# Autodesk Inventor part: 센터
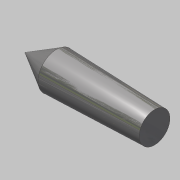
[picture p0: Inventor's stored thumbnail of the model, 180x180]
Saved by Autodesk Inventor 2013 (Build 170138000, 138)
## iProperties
Created: 2019-10
Part Number: 센터
Material: 스테인리스강
Document SubType Name: Modeling
Designer: mduedu
Density: 1 g/cm^3
Author: mduedu
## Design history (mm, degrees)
sketch "스케치1"
  geometry: L1 (0, 0)-(-31.5, 0); L2 (-31.5, 0)-(-31.5, -0.125); L3 (-31.5, -0.125)-(-23.922, -4.5); L4 (-23.922, -4.5)-(0, -3.751); L5 (0, -3.751)-(0, 0)
  constraints: 10 end point, 1 horizontal, 1 parallel, 1 perpendicular
  dimensions: "d0" = 31.5 distance of L1.start L1.end; "d1" = 7.502 diameter of L4.end L1; "d2" = 30 deg angle of L1 L3; "d3" = 7.578 horizontal distance of L2.end L3.end; "d5" = 0.25 diameter of L2.end L1; "d6" = 23.922 horizontal distance of L3.end L4.end (derived); "d7" = 9.00032 diameter of L3.end L1 (derived)
revolve "회전1" sketch "스케치1" stored, may be unused: angle "d8" = 90 deg
node "솔리드1"
